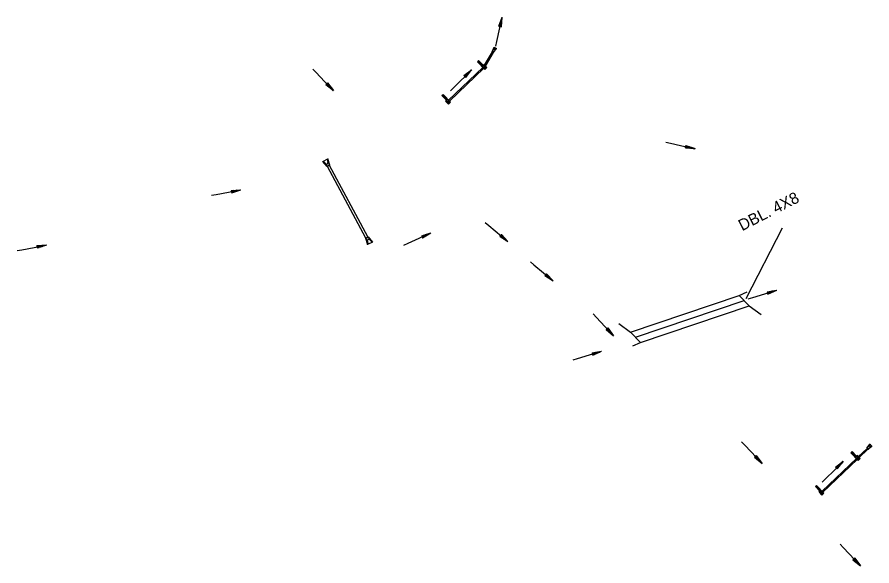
# Model space of a CAD drawing. Extents: x 1308292 to 1312792, y 238563 to 242743.
# Drawn here: x 1310663 to 1311710, y 239963 to 240636 of the extents above; entities that cross this region are included whole.
import ezdxf

# ---------------------------------------------------------------- set-up
doc = ezdxf.new("R2010")
doc.units = 0
for name, color, linetype in [('R_Box Culvert', 7, 'Continuous'), ('R_BRIDGE OLD', 7, 'Continuous'), ('R_Drop Inlet', 7, 'Continuous'), ('R_FES', 7, 'Continuous'), ('R_Flow Arrows', 7, 'Continuous'), ('R_Pipe Culvert', 7, 'Continuous')]:
    doc.layers.add(name, color=color, linetype=linetype)

msp = doc.modelspace()

# ---------------------------------------------------------------- linework, layer by layer
at = {"layer": 'R_Box Culvert'}
for p, q in [((1311547.8, 240294.8), (1311557.5, 240299)), ((1311414.8, 240249.8), (1311547.8, 240294.8)), ((1311420.9, 240243.4), (1311553.9, 240288.4)), ((1311547.8, 240294.8), (1311560, 240282)), ((1311427, 240237.1), (1311560, 240282)), ((1311560, 240282), (1311574.5, 240271.3)), ((1311400.3, 240260.5), (1311414.8, 240249.8)), ((1311414.8, 240249.8), (1311427, 240237.1)), ((1311417.4, 240232.8), (1311427, 240237.1))]:
    msp.add_line(p, q, dxfattribs=at)
at = {"layer": 'R_BRIDGE OLD'}
msp.add_line((1311556.4, 240290.8), (1311600.8, 240377.7), dxfattribs=at)
at = {"layer": 'R_Drop Inlet'}
for p, q in [((1311228.5, 240582.6), (1311227.1, 240581.2)), ((1311236.1, 240571.8), (1311227.1, 240581.2)), ((1311228.5, 240581.9), (1311227.8, 240581.2)), ((1311236.1, 240572.5), (1311227.8, 240581.2)), ((1311234.1, 240576.8), (1311228.5, 240582.6)), ((1311234.1, 240576.1), (1311228.5, 240581.9)), ((1311235.2, 240577.8), (1311234.1, 240576.8)), ((1311235.1, 240577.1), (1311234.1, 240576.1)), ((1311237.9, 240574.2), (1311235.1, 240577.1)), ((1311238.6, 240574.2), (1311235.2, 240577.8)), ((1311237.9, 240574.2), (1311236.1, 240572.5)), ((1311238.6, 240574.2), (1311236.1, 240571.8)), ((1311183.7, 240539.8), (1311185.1, 240541.2)), ((1311189.2, 240534), (1311183.7, 240539.8)), ((1311184.4, 240539.8), (1311185.1, 240540.5)), ((1311189.9, 240534), (1311184.4, 240539.8)), ((1311194.1, 240531.8), (1311185.1, 240541.2)), ((1311193.4, 240531.8), (1311185.1, 240540.5)), ((1311188.1, 240533), (1311189.2, 240534)), ((1311191.6, 240529.3), (1311188.1, 240533)), ((1311188.8, 240532.9), (1311189.9, 240534)), ((1311191.6, 240530), (1311188.8, 240532.9)), ((1311191.6, 240530), (1311193.4, 240531.8)), ((1311191.6, 240529.3), (1311194.1, 240531.8)), ((1311686, 240103.4), (1311684.5, 240102)), ((1311693.5, 240092.6), (1311684.5, 240102)), ((1311686, 240102.6), (1311685.2, 240102)), ((1311693.5, 240093.3), (1311685.2, 240102)), ((1311691.5, 240097.6), (1311686, 240103.4)), ((1311691.5, 240096.9), (1311686, 240102.6)), ((1311692.6, 240098.6), (1311691.5, 240097.6)), ((1311696, 240095), (1311692.6, 240098.6)), ((1311692.6, 240097.9), (1311691.5, 240096.9)), ((1311695.3, 240095), (1311692.6, 240097.9)), ((1311695.3, 240095), (1311693.5, 240093.3)), ((1311696, 240095), (1311693.5, 240092.6)), ((1311641.1, 240060.5), (1311642.6, 240061.9)), ((1311646.6, 240054.8), (1311641.1, 240060.5)), ((1311641.8, 240060.5), (1311642.6, 240061.2)), ((1311647.4, 240054.7), (1311641.8, 240060.5)), ((1311651.5, 240052.5), (1311642.6, 240061.9)), ((1311650.8, 240052.5), (1311642.6, 240061.2)), ((1311645.6, 240053.7), (1311646.6, 240054.8)), ((1311649, 240050.1), (1311645.6, 240053.7)), ((1311646.3, 240053.7), (1311647.4, 240054.7)), ((1311649, 240050.8), (1311646.3, 240053.7)), ((1311649, 240050.8), (1311650.8, 240052.5)), ((1311649, 240050.1), (1311651.5, 240052.5))]:
    msp.add_line(p, q, dxfattribs=at)
for centre in [(1311235.6, 240574.8), (1311191.1, 240532.4), (1311693, 240095.6), (1311648.6, 240053.1)]:
    msp.add_circle(centre, 1, dxfattribs=at)
at = {"layer": 'R_FES'}
for p, q in [((1311245.4, 240593.5), (1311247.7, 240599.2)), ((1311245.6, 240593.6), (1311245.4, 240593.5)), ((1311245.4, 240593.5), (1311247, 240592.5)), ((1311245.6, 240593.6), (1311247.9, 240599.1)), ((1311245.6, 240593.6), (1311246.9, 240592.7)), ((1311246.9, 240592.7), (1311250.5, 240597.5)), ((1311246.9, 240592.7), (1311247, 240592.5)), ((1311247, 240592.5), (1311250.7, 240597.4)), ((1311247.6, 240597.3), (1311247.7, 240599.2)), ((1311247.9, 240599.1), (1311247.6, 240597.3)), ((1311247.7, 240599.2), (1311250.7, 240597.4)), ((1311249.2, 240596.4), (1311250.5, 240597.5)), ((1311250.7, 240597.4), (1311249.2, 240596.4)), ((1311038, 240459.1), (1311043.9, 240462.3)), ((1311043.2, 240452.6), (1311038, 240459.1)), ((1311041.6, 240456.1), (1311038, 240459.1)), ((1311038.3, 240459.3), (1311041.6, 240456.1)), ((1311043.3, 240453), (1311038.3, 240459.3)), ((1311046.4, 240454.4), (1311043.2, 240452.6)), ((1311046, 240454.5), (1311043.3, 240453)), ((1311044.2, 240457.7), (1311043.6, 240462.1)), ((1311046, 240454.5), (1311043.6, 240462.1)), ((1311046.4, 240454.4), (1311043.9, 240462.3)), ((1311043.9, 240462.3), (1311044.2, 240457.7)), ((1311046, 240454.5), (1311046.4, 240454.4)), ((1311043.3, 240453), (1311043.2, 240452.6)), ((1311090.2, 240364.9), (1311093.4, 240366.7)), ((1311090.2, 240364.9), (1311092.7, 240357.1)), ((1311090.6, 240364.8), (1311090.2, 240364.9)), ((1311090.6, 240364.8), (1311093.3, 240366.3)), ((1311090.6, 240364.8), (1311093, 240357.2)), ((1311092.4, 240361.6), (1311093, 240357.2)), ((1311092.7, 240357.1), (1311092.4, 240361.6)), ((1311098.6, 240360.2), (1311092.7, 240357.1)), ((1311093.3, 240366.3), (1311093.4, 240366.7)), ((1311093.3, 240366.3), (1311098.3, 240360)), ((1311093.4, 240366.7), (1311098.6, 240360.2)), ((1311095, 240363.2), (1311098.6, 240360.2)), ((1311098.3, 240360), (1311095, 240363.2)), ((1311704.1, 240107.5), (1311707.8, 240112.4)), ((1311704.4, 240107.5), (1311708, 240112.3)), ((1311705.4, 240106.4), (1311710.1, 240110)), ((1311705.5, 240106.1), (1311710.3, 240109.9)), ((1311707.2, 240110.6), (1311707.8, 240112.4)), ((1311708, 240112.3), (1311707.2, 240110.6)), ((1311707.8, 240112.4), (1311710.3, 240109.9)), ((1311708.6, 240109.3), (1311710.1, 240110)), ((1311710.3, 240109.9), (1311708.6, 240109.3)), ((1311704.1, 240107.5), (1311705.5, 240106.1)), ((1311704.4, 240107.5), (1311704.1, 240107.5)), ((1311704.4, 240107.5), (1311705.4, 240106.4)), ((1311705.4, 240106.4), (1311705.5, 240106.1))]:
    msp.add_line(p, q, dxfattribs=at)
for centre, radius, start, end in [((1311248.6, 240597.2), 1, 173.2568, 306.7875), ((1311042.5, 240457.5), 1.67, 234.888, 8.4187), ((1311094, 240361.8), 1.67, 54.888, 188.4187), ((1311708.2, 240110.3), 1, 158.8285, 292.3593)]:
    msp.add_arc(centre, radius, start, end, dxfattribs=at)
at = {"layer": 'R_Flow Arrows'}
for p, q in [((1311253.5, 240624.7), (1311257.3, 240635.9)), ((1311256.5, 240624.1), (1311257.3, 240635.9)), ((1311253.5, 240624.7), (1311256.5, 240624.1)), ((1311210.7, 240564.2), (1311220.1, 240571.4)), ((1311212.8, 240562), (1311220.1, 240571.4)), ((1311210.7, 240564.2), (1311212.8, 240562)), ((1311043.7, 240555.3), (1311041.5, 240553.2)), ((1311041.5, 240553.2), (1311050.8, 240545.8)), ((1311043.7, 240555.3), (1311050.8, 240545.8)), ((1311481.9, 240475.6), (1311482.5, 240478.6)), ((1311481.9, 240475.6), (1311493.7, 240474.7)), ((1311482.5, 240478.6), (1311493.7, 240474.7)), ((1310925.7, 240423.5), (1310937.6, 240424.3)), ((1310925.7, 240423.5), (1310926.3, 240420.6)), ((1310926.3, 240420.6), (1310937.6, 240424.3)), ((1311158.9, 240368), (1311170.2, 240371.4)), ((1311160.1, 240365.2), (1311170.2, 240371.4)), ((1311158.9, 240368), (1311160.1, 240365.2)), ((1311256.5, 240369.5), (1311254.5, 240367.2)), ((1311254.5, 240367.2), (1311264.5, 240360.7)), ((1311256.5, 240369.5), (1311264.5, 240360.7)), ((1310687.5, 240355.8), (1310699.3, 240356.6)), ((1310687.5, 240355.8), (1310688.1, 240352.9)), ((1310688.1, 240352.9), (1310699.3, 240356.6)), ((1311311.9, 240321.3), (1311309.9, 240319)), ((1311309.9, 240319), (1311319.8, 240312.5)), ((1311311.9, 240321.3), (1311319.8, 240312.5)), ((1311582.1, 240299.3), (1311593.8, 240301.3)), ((1311582.1, 240299.3), (1311583, 240296.4)), ((1311583, 240296.4), (1311593.8, 240301.3)), ((1311387, 240255), (1311384.8, 240252.9)), ((1311387, 240255), (1311393.9, 240245.4)), ((1311384.8, 240252.9), (1311393.9, 240245.4)), ((1311367.6, 240224.4), (1311379.2, 240226.4)), ((1311367.6, 240224.4), (1311368.5, 240221.4)), ((1311368.5, 240221.4), (1311379.2, 240226.4)), ((1311568.7, 240098.5), (1311566.5, 240096.4)), ((1311568.7, 240098.5), (1311575.7, 240088.9)), ((1311566.5, 240096.4), (1311575.7, 240088.9)), ((1311665.8, 240084.3), (1311675.2, 240091.5)), ((1311667.9, 240082.1), (1311675.2, 240091.5)), ((1311665.8, 240084.3), (1311667.9, 240082.1)), ((1311689.2, 239972.9), (1311687, 239970.8)), ((1311689.2, 239972.9), (1311696.1, 239963.2)), ((1311687, 239970.8), (1311696.1, 239963.2))]:
    msp.add_line(p, q, dxfattribs=at)
for points in [[(1311249.9, 240600.2), (1311251.1, 240605.8), (1311257.4, 240635.9)], [(1311254.7, 240624.4), (1311255.9, 240630.5), (1311256.5, 240633.7)], [(1311255.3, 240624.3), (1311256.5, 240630.4), (1311257.1, 240633.5)], [(1311253.8, 240624.6), (1311254.3, 240626.9)], [(1311254.1, 240624.6), (1311255, 240629.2)], [(1311254.4, 240624.5), (1311255.6, 240630.6), (1311255.8, 240631.4)], [(1311255.6, 240624.3), (1311256.8, 240630.4), (1311257, 240631.2)], [(1311255.9, 240624.2), (1311256.8, 240628.8)], [(1311256.2, 240624.1), (1311256.6, 240626.5)], [(1311025.6, 240572.2), (1311029.5, 240568), (1311050.7, 240545.7)], [(1311194.1, 240545.7), (1311198.2, 240549.8), (1311220.2, 240571.3)], [(1311211.6, 240563.3), (1311216, 240567.7), (1311218.2, 240569.9)], [(1311212, 240562.9), (1311216.4, 240567.3), (1311218.6, 240569.5)], [(1311210.9, 240563.9), (1311212.6, 240565.6)], [(1311211.1, 240563.7), (1311214.5, 240567.1)], [(1311211.3, 240563.5), (1311215.7, 240567.9), (1311216.3, 240568.5)], [(1311212.2, 240562.7), (1311216.6, 240567), (1311217.2, 240567.6)], [(1311212.4, 240562.4), (1311215.7, 240565.8)], [(1311212.6, 240562.2), (1311214.3, 240563.9)], [(1311041.7, 240553.4), (1311043.4, 240551.7)], [(1311041.9, 240553.6), (1311045.2, 240550.2)], [(1311042.2, 240553.8), (1311046.5, 240549.4), (1311047.1, 240548.8)], [(1311042.4, 240554), (1311046.7, 240549.6), (1311048.9, 240547.3)], [(1311042.8, 240554.5), (1311047.1, 240550), (1311049.3, 240547.7)], [(1311043, 240554.7), (1311047.4, 240550.2), (1311047.9, 240549.6)], [(1311043.3, 240554.9), (1311046.5, 240551.5)], [(1311043.5, 240555.1), (1311045.1, 240553.4)], [(1311458, 240482.5), (1311463.6, 240481.2), (1311493.6, 240474.6)], [(1311481.9, 240475.9), (1311484.2, 240475.5)], [(1311482, 240476.5), (1311488.1, 240475.3), (1311488.9, 240475.1)], [(1311482, 240476.2), (1311486.6, 240475.3)], [(1311482.1, 240476.8), (1311488.2, 240475.5), (1311491.3, 240474.9)], [(1311482.2, 240477.4), (1311488.3, 240476.1), (1311491.4, 240475.5)], [(1311482.3, 240477.7), (1311488.4, 240476.4), (1311489.2, 240476.3)], [(1311482.4, 240478.3), (1311484.7, 240477.8)], [(1311482.4, 240478), (1311487, 240477.1)], [(1310901.7, 240417.5), (1310907.4, 240418.5), (1310937.6, 240424.2)], [(1310925.8, 240423.2), (1310928.1, 240423.7)], [(1310925.9, 240422.6), (1310932, 240423.8), (1310932.8, 240424)], [(1310925.9, 240422.9), (1310930.5, 240423.8)], [(1310926, 240422.3), (1310932.1, 240423.5), (1310935.2, 240424.1)], [(1310926.1, 240421.7), (1310932.2, 240422.9), (1310935.3, 240423.6)], [(1310926.1, 240421.4), (1310932.2, 240422.6), (1310933.1, 240422.8)], [(1310926.2, 240421.1), (1310930.8, 240422.1)], [(1310926.3, 240420.9), (1310928.6, 240421.3)], [(1311236.6, 240384.3), (1311241, 240380.6), (1311264.5, 240360.7)], [(1311136.9, 240356.5), (1311142.2, 240358.8), (1311170.2, 240371.4)], [(1311159.4, 240366.9), (1311165.1, 240369.4), (1311168, 240370.7)], [(1311159.6, 240366.3), (1311165.3, 240368.8), (1311168.2, 240370.1)], [(1311159, 240367.7), (1311161.2, 240368.7)], [(1311159.1, 240367.4), (1311163.4, 240369.3)], [(1311159.3, 240367.1), (1311164.9, 240369.7), (1311165.7, 240370)], [(1311159.8, 240366), (1311165.4, 240368.6), (1311166.2, 240368.9)], [(1311159.9, 240365.8), (1311164.2, 240367.7)], [(1311160, 240365.5), (1311162.2, 240366.4)], [(1311254.7, 240367.4), (1311256.5, 240365.9)], [(1311254.9, 240367.7), (1311258.5, 240364.6)], [(1311255.1, 240367.9), (1311259.8, 240363.9), (1311260.5, 240363.3)], [(1311255.3, 240368.1), (1311260, 240364.1), (1311262.5, 240362)], [(1311255.7, 240368.6), (1311260.4, 240364.6), (1311262.9, 240362.5)], [(1311255.9, 240368.8), (1311260.6, 240364.8), (1311261.3, 240364.2)], [(1311256.1, 240369), (1311259.7, 240366)], [(1311256.3, 240369.3), (1311258.1, 240367.8)], [(1310663.4, 240349.8), (1310669.1, 240350.8), (1310699.3, 240356.5)], [(1310687.5, 240355.5), (1310689.8, 240356)], [(1310687.6, 240354.9), (1310693.7, 240356.1), (1310694.6, 240356.3)], [(1310687.6, 240355.2), (1310692.2, 240356.1)], [(1310687.7, 240354.6), (1310693.8, 240355.8), (1310696.9, 240356.4)], [(1310687.8, 240354), (1310693.9, 240355.2), (1310697, 240355.9)], [(1310687.9, 240353.7), (1310694, 240354.9), (1310694.8, 240355.1)], [(1310687.9, 240353.4), (1310692.5, 240354.4)], [(1310688, 240353.2), (1310690.3, 240353.6)], [(1311292, 240336.1), (1311296.4, 240332.4), (1311319.8, 240312.5)], [(1311310.1, 240319.2), (1311311.9, 240317.7)], [(1311310.3, 240319.4), (1311313.9, 240316.4)], [(1311310.5, 240319.7), (1311315.2, 240315.7), (1311315.9, 240315.1)], [(1311310.7, 240319.9), (1311315.4, 240315.9), (1311317.8, 240313.8)], [(1311311.1, 240320.4), (1311315.8, 240316.3), (1311318.2, 240314.3)], [(1311311.3, 240320.6), (1311316, 240316.6), (1311316.6, 240316)], [(1311311.5, 240320.8), (1311315.1, 240317.8)], [(1311311.7, 240321.1), (1311313.5, 240319.5)], [(1311558.9, 240290.7), (1311564.4, 240292.4), (1311593.9, 240301.2)], [(1311582.2, 240299), (1311584.5, 240299.7)], [(1311582.3, 240298.7), (1311586.8, 240300.1)], [(1311582.4, 240298.4), (1311588.3, 240300.3), (1311589.1, 240300.5)], [(1311582.5, 240298.1), (1311588.4, 240300), (1311591.5, 240300.9)], [(1311582.7, 240297.6), (1311588.6, 240299.4), (1311591.7, 240300.3)], [(1311582.8, 240297.3), (1311588.7, 240299.1), (1311589.5, 240299.4)], [(1311582.9, 240297), (1311587.4, 240298.4)], [(1311583, 240296.7), (1311585.2, 240297.4)], [(1311368.9, 240272), (1311372.9, 240267.8), (1311393.9, 240245.4)], [(1311385, 240253.1), (1311386.6, 240251.4)], [(1311385.2, 240253.3), (1311388.4, 240249.9)], [(1311385.4, 240253.5), (1311389.7, 240249), (1311390.2, 240248.4)], [(1311385.6, 240253.7), (1311389.9, 240249.2), (1311392.1, 240246.9)], [(1311386.1, 240254.2), (1311390.3, 240249.6), (1311392.5, 240247.3)], [(1311386.3, 240254.4), (1311390.6, 240249.8), (1311391.1, 240249.2)], [(1311386.5, 240254.6), (1311389.7, 240251.1)], [(1311386.8, 240254.8), (1311388.4, 240253.1)], [(1311344.4, 240215.7), (1311349.9, 240217.4), (1311379.3, 240226.3)], [(1311367.7, 240224.1), (1311369.9, 240224.8)], [(1311367.8, 240223.8), (1311372.2, 240225.2)], [(1311367.9, 240223.2), (1311373.9, 240225), (1311376.9, 240226)], [(1311367.9, 240223.5), (1311373.8, 240225.3), (1311374.6, 240225.6)], [(1311368.1, 240222.6), (1311374.1, 240224.5), (1311377.1, 240225.4)], [(1311368.2, 240222.3), (1311374.1, 240224.2), (1311374.9, 240224.4)], [(1311368.3, 240222), (1311372.8, 240223.4)], [(1311368.4, 240221.7), (1311370.6, 240222.4)], [(1311550.7, 240115.5), (1311554.7, 240111.3), (1311575.7, 240088.9)], [(1311568.3, 240098.1), (1311571.5, 240094.6)], [(1311568.5, 240098.3), (1311570.1, 240096.6)], [(1311566.7, 240096.6), (1311568.3, 240094.9)], [(1311567, 240096.8), (1311570.2, 240093.4)], [(1311567.2, 240097), (1311571.4, 240092.5), (1311572, 240091.9)], [(1311567.4, 240097.2), (1311571.6, 240092.7), (1311573.8, 240090.4)], [(1311567.8, 240097.7), (1311572.1, 240093.1), (1311574.3, 240090.8)], [(1311568.1, 240097.9), (1311572.3, 240093.3), (1311572.9, 240092.7)], [(1311649.2, 240065.8), (1311653.3, 240069.9), (1311675.3, 240091.4)], [(1311666.4, 240083.6), (1311670.8, 240088), (1311671.4, 240088.6)], [(1311666.7, 240083.4), (1311671, 240087.8), (1311673.3, 240090)], [(1311667.1, 240083), (1311671.5, 240087.4), (1311673.7, 240089.6)], [(1311667.3, 240082.8), (1311671.7, 240087.1), (1311672.3, 240087.7)], [(1311666, 240084), (1311667.7, 240085.7)], [(1311666.2, 240083.8), (1311669.5, 240087.1)], [(1311667.5, 240082.5), (1311670.8, 240085.9)], [(1311667.7, 240082.3), (1311669.4, 240084)], [(1311671.2, 239989.9), (1311675.1, 239985.7), (1311696.1, 239963.2)], [(1311688.8, 239972.4), (1311692, 239969)], [(1311689, 239972.6), (1311690.6, 239970.9)], [(1311687.2, 239971), (1311688.8, 239969.3)], [(1311687.4, 239971.2), (1311690.7, 239967.8)], [(1311687.7, 239971.4), (1311691.9, 239966.9), (1311692.5, 239966.3)], [(1311687.9, 239971.6), (1311692.1, 239967.1), (1311694.3, 239964.7)], [(1311688.3, 239972), (1311692.6, 239967.5), (1311694.8, 239965.2)], [(1311688.6, 239972.2), (1311692.8, 239967.7), (1311693.4, 239967.1)]]:
    msp.add_lwpolyline(points, dxfattribs=at)
at = {"layer": 'R_Pipe Culvert'}
for p, q in [((1311236, 240577), (1311245.5, 240593.4)), ((1311237.1, 240575.8), (1311246.8, 240592.6)), ((1311191.9, 240534.1), (1311233.8, 240574.2)), ((1311192.9, 240533), (1311234.9, 240573.1)), ((1311093.1, 240366.5), (1311046.1, 240454.2)), ((1311090.5, 240365.1), (1311043.5, 240452.8)), ((1311693.8, 240097.3), (1311704.3, 240107.3)), ((1311694.8, 240096.3), (1311705.3, 240106.3)), ((1311649.3, 240054.9), (1311691.3, 240094.9)), ((1311650.3, 240053.8), (1311692.3, 240093.8))]:
    msp.add_line(p, q, dxfattribs=at)

# ---------------------------------------------------------------- texts
at = {"layer": 'R_BRIDGE OLD'}
msp.add_text('DBL. 4X8', height=14, rotation=27.132, dxfattribs=at).set_placement((1311551.3, 240373.4))

doc.saveas('drawing.dxf')
